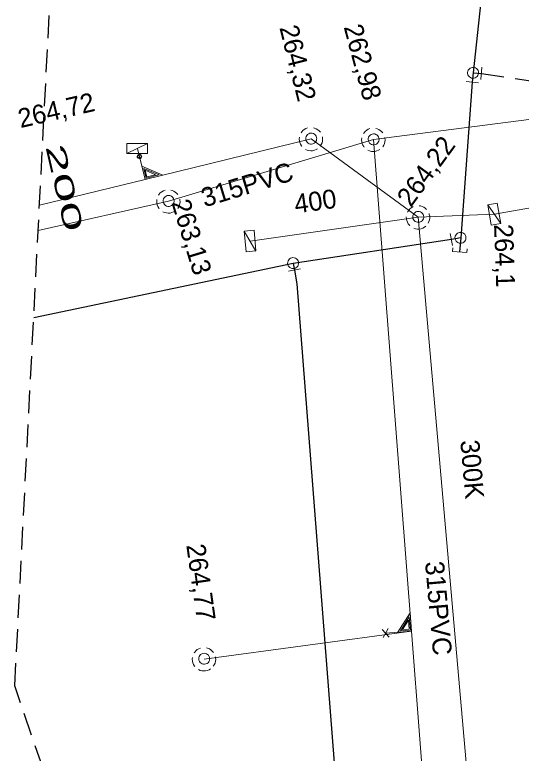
# Model space of a CAD drawing. Extents: x -732074 to -731966, y -1048695 to -1047982.
# Drawn here: x -732074 to -732052.65, y -1048415.55 to -1048384.41 of the extents above; entities that cross this region are included whole.
import ezdxf

# ---------------------------------------------------------------- set-up
doc = ezdxf.new("R2010")
doc.units = 0
doc.header["$LTSCALE"] = 0.32
doc.linetypes.add('LONG_DASHED', pattern=[7.5, 6, -1.5])
doc.linetypes.add('MEDIUM_DASHED', pattern=[4.5, 3, -1.5])
doc.layers.add('1', color=7, linetype='Continuous')
for name, color, linetype, lineweight in [('18', 7, 'Continuous', 13), ('20', 7, 'Continuous', 13), ('49', 7, 'Continuous', 13), ('63', 7, 'MEDIUM_DASHED', 25), ('8', 7, 'Continuous', 13)]:
    doc.layers.add(name, color=color, linetype=linetype, lineweight=lineweight)

msp = doc.modelspace()

# ---------------------------------------------------------------- linework, layer by layer
at = {"layer": '18'}
for p, q in [((-732069.271, -1048390.25), (-732068.397, -1048389.838)), ((-732054.062, -1048392.419), (-732053.508, -1048393.211)), ((-732064.32, -1048393.539), (-732063.829, -1048394.371)), ((-732058.507, -1048410.339), (-732058.213, -1048410.653)), ((-732058.468, -1048410.676), (-732058.253, -1048410.288))]:
    msp.add_line(p, q, dxfattribs=at)
for points in [[(-732061.653, -1048389.177), (-732061.724, -1048389.205), (-732061.791, -1048389.244), (-732061.851, -1048389.292), (-732061.902, -1048389.349), (-732061.926, -1048389.383)], [(-732061.112, -1048389.36), (-732061.162, -1048389.302), (-732061.22, -1048389.252), (-732061.285, -1048389.211), (-732061.356, -1048389.182), (-732061.405, -1048389.168)], [(-732059.023, -1048389.207), (-732059.094, -1048389.235), (-732059.161, -1048389.274), (-732059.221, -1048389.322), (-732059.272, -1048389.379), (-732059.296, -1048389.413)], [(-732058.482, -1048389.39), (-732058.532, -1048389.332), (-732058.59, -1048389.282), (-732058.655, -1048389.241), (-732058.726, -1048389.212), (-732058.775, -1048389.198)], [(-732061.998, -1048389.569), (-732062.004, -1048389.646), (-732061.999, -1048389.723), (-732061.982, -1048389.798), (-732061.953, -1048389.869), (-732061.913, -1048389.935), (-732061.897, -1048389.957)], [(-732061.117, -1048389.946), (-732061.076, -1048389.881), (-732061.045, -1048389.811), (-732061.026, -1048389.736), (-732061.018, -1048389.66), (-732061.023, -1048389.583), (-732061.029, -1048389.548)], [(-732058.487, -1048389.976), (-732058.446, -1048389.911), (-732058.415, -1048389.841), (-732058.396, -1048389.766), (-732058.388, -1048389.69), (-732058.393, -1048389.613), (-732058.399, -1048389.578)], [(-732059.368, -1048389.599), (-732059.374, -1048389.676), (-732059.369, -1048389.753), (-732059.352, -1048389.828), (-732059.323, -1048389.899), (-732059.282, -1048389.965), (-732059.267, -1048389.987)], [(-732061.74, -1048390.086), (-732061.67, -1048390.117), (-732061.595, -1048390.136), (-732061.519, -1048390.143), (-732061.442, -1048390.138), (-732061.367, -1048390.121), (-732061.295, -1048390.093), (-732061.235, -1048390.058)], [(-732059.11, -1048390.116), (-732059.04, -1048390.147), (-732058.965, -1048390.166), (-732058.889, -1048390.173), (-732058.812, -1048390.168), (-732058.737, -1048390.151), (-732058.665, -1048390.123), (-732058.605, -1048390.088)], [(-732068.763, -1048390.288), (-732068.503, -1048391.352), (-732067.754, -1048391.169), (-732068.64, -1048390.79)], [(-732068.562, -1048390.894), (-732068.464, -1048391.298), (-732067.914, -1048391.163), (-732068.563, -1048390.892)], [(-732068.497, -1048390.963), (-732068.428, -1048391.247), (-732068.067, -1048391.159), (-732068.498, -1048390.964)], [(-732067.663, -1048391.807), (-732067.734, -1048391.835), (-732067.801, -1048391.874), (-732067.861, -1048391.922), (-732067.912, -1048391.979), (-732067.936, -1048392.013)], [(-732067.122, -1048391.99), (-732067.172, -1048391.932), (-732067.23, -1048391.882), (-732067.295, -1048391.841), (-732067.366, -1048391.812), (-732067.415, -1048391.798)], [(-732068.008, -1048392.199), (-732068.014, -1048392.276), (-732068.009, -1048392.353), (-732067.992, -1048392.428), (-732067.963, -1048392.499), (-732067.923, -1048392.565), (-732067.907, -1048392.587)], [(-732067.127, -1048392.576), (-732067.086, -1048392.511), (-732067.055, -1048392.441), (-732067.036, -1048392.366), (-732067.028, -1048392.29), (-732067.033, -1048392.213), (-732067.039, -1048392.178)], [(-732067.75, -1048392.716), (-732067.68, -1048392.747), (-732067.605, -1048392.766), (-732067.529, -1048392.773), (-732067.452, -1048392.768), (-732067.377, -1048392.751), (-732067.305, -1048392.723), (-732067.245, -1048392.688)], [(-732057.196, -1048392.499), (-732057.263, -1048392.535), (-732057.325, -1048392.582), (-732057.378, -1048392.636), (-732057.422, -1048392.699), (-732057.442, -1048392.736)], [(-732056.637, -1048392.616), (-732056.693, -1048392.564), (-732056.757, -1048392.521), (-732056.826, -1048392.488), (-732056.9, -1048392.468), (-732056.95, -1048392.46)], [(-732057.491, -1048392.929), (-732057.488, -1048393.006), (-732057.474, -1048393.082), (-732057.448, -1048393.154), (-732057.411, -1048393.221), (-732057.363, -1048393.282), (-732057.345, -1048393.302)], [(-732056.572, -1048393.198), (-732056.539, -1048393.129), (-732056.516, -1048393.055), (-732056.506, -1048392.979), (-732056.507, -1048392.902), (-732056.522, -1048392.827), (-732056.532, -1048392.792)], [(-732057.174, -1048393.411), (-732057.1, -1048393.434), (-732057.024, -1048393.444), (-732056.947, -1048393.442), (-732056.871, -1048393.428), (-732056.799, -1048393.402), (-732056.731, -1048393.365), (-732056.675, -1048393.323)], [(-732058.366, -1048410.49), (-732057.273, -1048410.406), (-732057.333, -1048409.637), (-732057.85, -1048410.45)], [(-732057.736, -1048410.39), (-732057.321, -1048410.358), (-732057.365, -1048409.795), (-732057.737, -1048410.39)], [(-732057.656, -1048410.337), (-732057.366, -1048410.315), (-732057.394, -1048409.945), (-732057.656, -1048410.339)], [(-732066.163, -1048411.117), (-732066.234, -1048411.145), (-732066.301, -1048411.184), (-732066.361, -1048411.232), (-732066.412, -1048411.289), (-732066.436, -1048411.323)], [(-732065.622, -1048411.3), (-732065.672, -1048411.242), (-732065.73, -1048411.192), (-732065.795, -1048411.151), (-732065.866, -1048411.122), (-732065.915, -1048411.108)], [(-732066.508, -1048411.509), (-732066.514, -1048411.586), (-732066.509, -1048411.663), (-732066.492, -1048411.738), (-732066.463, -1048411.809), (-732066.423, -1048411.875), (-732066.407, -1048411.897)], [(-732065.627, -1048411.886), (-732065.586, -1048411.821), (-732065.555, -1048411.751), (-732065.536, -1048411.676), (-732065.528, -1048411.6), (-732065.533, -1048411.523), (-732065.539, -1048411.488)], [(-732066.25, -1048412.026), (-732066.18, -1048412.057), (-732066.105, -1048412.076), (-732066.029, -1048412.083), (-732065.952, -1048412.078), (-732065.877, -1048412.061), (-732065.805, -1048412.033), (-732065.745, -1048411.998)]]:
    msp.add_lwpolyline(points, dxfattribs=at)
for points in [[(-732061.269, -1048389.629), (-732061.275, -1048389.577), (-732061.293, -1048389.527), (-732061.321, -1048389.483), (-732061.359, -1048389.446), (-732061.404, -1048389.419), (-732061.454, -1048389.403), (-732061.506, -1048389.398), (-732061.558, -1048389.405), (-732061.607, -1048389.424), (-732061.651, -1048389.454), (-732061.686, -1048389.493), (-732061.712, -1048389.538), (-732061.727, -1048389.589), (-732061.73, -1048389.641), (-732061.722, -1048389.693), (-732061.701, -1048389.741), (-732061.671, -1048389.784), (-732061.631, -1048389.819), (-732061.585, -1048389.843), (-732061.534, -1048389.857), (-732061.482, -1048389.859), (-732061.43, -1048389.849), (-732061.382, -1048389.827), (-732061.34, -1048389.795), (-732061.307, -1048389.755), (-732061.283, -1048389.708), (-732061.271, -1048389.657)], [(-732058.639, -1048389.659), (-732058.645, -1048389.607), (-732058.663, -1048389.557), (-732058.691, -1048389.513), (-732058.729, -1048389.476), (-732058.774, -1048389.449), (-732058.824, -1048389.433), (-732058.876, -1048389.428), (-732058.928, -1048389.435), (-732058.977, -1048389.454), (-732059.021, -1048389.484), (-732059.056, -1048389.523), (-732059.082, -1048389.568), (-732059.097, -1048389.619), (-732059.1, -1048389.671), (-732059.092, -1048389.723), (-732059.071, -1048389.771), (-732059.041, -1048389.814), (-732059.001, -1048389.849), (-732058.955, -1048389.873), (-732058.904, -1048389.887), (-732058.852, -1048389.889), (-732058.8, -1048389.879), (-732058.752, -1048389.857), (-732058.71, -1048389.825), (-732058.677, -1048389.785), (-732058.653, -1048389.738), (-732058.641, -1048389.687)], [(-732069.275, -1048389.838), (-732068.401, -1048389.838), (-732068.401, -1048390.25), (-732069.275, -1048390.25)], [(-732068.649, -1048390.357), (-732068.662, -1048390.326), (-732068.686, -1048390.302), (-732068.716, -1048390.288), (-732068.749, -1048390.286), (-732068.781, -1048390.295), (-732068.808, -1048390.315), (-732068.827, -1048390.343), (-732068.834, -1048390.376), (-732068.83, -1048390.409), (-732068.814, -1048390.439), (-732068.789, -1048390.46), (-732068.758, -1048390.472), (-732068.724, -1048390.472), (-732068.693, -1048390.461), (-732068.667, -1048390.44), (-732068.651, -1048390.41), (-732068.646, -1048390.377)], [(-732068.674, -1048390.365), (-732068.687, -1048390.34), (-732068.709, -1048390.321), (-732068.735, -1048390.313), (-732068.764, -1048390.318), (-732068.787, -1048390.333), (-732068.803, -1048390.357), (-732068.808, -1048390.385), (-732068.8, -1048390.412), (-732068.781, -1048390.434), (-732068.756, -1048390.446), (-732068.727, -1048390.447), (-732068.702, -1048390.437), (-732068.683, -1048390.416), (-732068.673, -1048390.389)], [(-732067.279, -1048392.259), (-732067.285, -1048392.207), (-732067.303, -1048392.157), (-732067.331, -1048392.113), (-732067.369, -1048392.076), (-732067.414, -1048392.049), (-732067.464, -1048392.033), (-732067.516, -1048392.028), (-732067.568, -1048392.035), (-732067.617, -1048392.054), (-732067.661, -1048392.084), (-732067.696, -1048392.123), (-732067.722, -1048392.168), (-732067.737, -1048392.219), (-732067.74, -1048392.271), (-732067.732, -1048392.323), (-732067.711, -1048392.371), (-732067.681, -1048392.414), (-732067.641, -1048392.449), (-732067.595, -1048392.473), (-732067.544, -1048392.487), (-732067.492, -1048392.489), (-732067.44, -1048392.479), (-732067.392, -1048392.457), (-732067.35, -1048392.425), (-732067.317, -1048392.385), (-732067.293, -1048392.338), (-732067.281, -1048392.287)], [(-732053.656, -1048392.346), (-732053.509, -1048393.207), (-732053.915, -1048393.277), (-732054.062, -1048392.416)], [(-732056.757, -1048392.929), (-732056.764, -1048392.877), (-732056.781, -1048392.827), (-732056.809, -1048392.783), (-732056.848, -1048392.746), (-732056.892, -1048392.719), (-732056.943, -1048392.703), (-732056.995, -1048392.698), (-732057.046, -1048392.705), (-732057.095, -1048392.724), (-732057.139, -1048392.754), (-732057.174, -1048392.793), (-732057.201, -1048392.838), (-732057.215, -1048392.889), (-732057.218, -1048392.941), (-732057.21, -1048392.993), (-732057.19, -1048393.041), (-732057.159, -1048393.084), (-732057.12, -1048393.119), (-732057.073, -1048393.143), (-732057.022, -1048393.157), (-732056.97, -1048393.159), (-732056.919, -1048393.149), (-732056.87, -1048393.127), (-732056.828, -1048393.095), (-732056.796, -1048393.055), (-732056.772, -1048393.008), (-732056.759, -1048392.957)], [(-732063.91, -1048393.497), (-732063.83, -1048394.367), (-732064.24, -1048394.405), (-732064.32, -1048393.535)], [(-732065.779, -1048411.569), (-732065.785, -1048411.517), (-732065.803, -1048411.467), (-732065.831, -1048411.423), (-732065.869, -1048411.386), (-732065.914, -1048411.359), (-732065.964, -1048411.343), (-732066.016, -1048411.338), (-732066.068, -1048411.345), (-732066.117, -1048411.364), (-732066.161, -1048411.394), (-732066.196, -1048411.433), (-732066.222, -1048411.478), (-732066.237, -1048411.529), (-732066.24, -1048411.581), (-732066.232, -1048411.633), (-732066.211, -1048411.681), (-732066.181, -1048411.724), (-732066.141, -1048411.759), (-732066.095, -1048411.783), (-732066.044, -1048411.797), (-732065.992, -1048411.799), (-732065.94, -1048411.789), (-732065.892, -1048411.767), (-732065.85, -1048411.735), (-732065.817, -1048411.695), (-732065.793, -1048411.648), (-732065.781, -1048411.597)]]:
    msp.add_lwpolyline(points, close=True, dxfattribs=at)
at = {"layer": '20'}
for p, q in [((-732067.51, -1048392.27), (-732058.87, -1048389.67)), ((-732067.51, -1048392.27), (-732058.87, -1048389.67)), ((-732061.5, -1048389.64), (-732056.989, -1048392.94)), ((-732061.5, -1048389.64), (-732056.989, -1048392.94)), ((-732073.01, -1048393.503), (-732067.51, -1048392.27)), ((-732073.01, -1048393.503), (-732067.51, -1048392.27)), ((-732064.07, -1048393.96), (-732056.989, -1048392.94)), ((-732064.07, -1048393.96), (-732056.989, -1048392.94)), ((-732056.989, -1048392.94), (-732053.78, -1048392.82)), ((-732056.989, -1048392.94), (-732053.78, -1048392.82)), ((-732053.92, -1048427.8), (-732056.989, -1048392.94)), ((-732053.92, -1048427.8), (-732056.989, -1048392.94))]:
    msp.add_line(p, q, dxfattribs=at)
at = {"layer": '20', "linetype": 'LONG_DASHED'}
msp.add_line((-732053.78, -1048392.82), (-732046.694, -1048391.564), dxfattribs=at)
msp.add_line((-732053.78, -1048392.82), (-732046.694, -1048391.564), dxfattribs=at)
at = {"layer": '20'}
for points in [[(-732058.87, -1048389.67), (-732043.269, -1048387.661), (-732041.707, -1048387.459)], [(-732058.87, -1048389.67), (-732043.269, -1048387.661), (-732041.707, -1048387.459)], [(-732072.956, -1048392.443), (-732068.504, -1048391.354), (-732061.5, -1048389.64)], [(-732072.956, -1048392.443), (-732068.504, -1048391.354), (-732061.5, -1048389.64)], [(-732055.579, -1048432.35), (-732056.217, -1048424.068), (-732057.272, -1048410.408), (-732058.87, -1048389.67)], [(-732055.579, -1048432.35), (-732056.217, -1048424.068), (-732057.272, -1048410.408), (-732058.87, -1048389.67)]]:
    msp.add_lwpolyline(points, dxfattribs=at)
at = {"layer": '49'}
for p, q in [((-732068.829, -1048390.04), (-732068.504, -1048391.354)), ((-732068.829, -1048390.04), (-732068.504, -1048391.354)), ((-732066.01, -1048411.58), (-732057.272, -1048410.408)), ((-732066.01, -1048411.58), (-732057.272, -1048410.408))]:
    msp.add_line(p, q, dxfattribs=at)
at = {"layer": '63'}
msp.add_lwpolyline([(-732022.871, -1048561.909), (-732073.995, -1048412.717), (-732073.996, -1048412.715), (-732073.996, -1048412.713), (-732069.268, -1048320.574)], dxfattribs=at)
at = {"layer": '8'}
for p, q in [((-732054.303, -1048386.621), (-732054.354, -1048387.136)), ((-732054.451, -1048387.277), (-732054.966, -1048387.222)), ((-732055.539, -1048394.143), (-732055.638, -1048393.636)), ((-732061.951, -1048395.125), (-732062.458, -1048395.222))]:
    msp.add_line(p, q, dxfattribs=at)
at = {"layer": '8', "lineweight": 25}
for p, q in [((-732054.669, -1048386.855), (-732054.71, -1048387.25)), ((-732054.669, -1048386.855), (-732054.329, -1048386.88)), ((-732054.71, -1048387.25), (-732055.199, -1048393.814)), ((-732055.589, -1048393.89), (-732062.264, -1048394.892)), ((-732055.199, -1048393.814), (-732055.589, -1048393.89)), ((-732062.264, -1048394.892), (-732073.199, -1048397.189)), ((-732062.264, -1048394.892), (-732062.206, -1048395.174))]:
    msp.add_line(p, q, dxfattribs=at)
at = {"layer": '8', "linetype": 'MEDIUM_DASHED', "lineweight": 25}
for p, q in [((-732054.329, -1048386.88), (-732048.844, -1048387.71)), ((-732055.199, -1048393.814), (-732055.245, -1048394.411))]:
    msp.add_line(p, q, dxfattribs=at)
at = {"layer": '8', "lineweight": 25}
for points in [[(-732044.76, -1048309.89), (-732045.27, -1048311.67), (-732051.3, -1048355.421), (-732054.669, -1048386.855)], [(-732062.206, -1048395.174), (-732062.1, -1048395.76), (-732060.37, -1048418.12)]]:
    msp.add_lwpolyline(points, dxfattribs=at)
at = {"layer": '8'}
for points in [[(-732054.654, -1048386.624), (-732054.707, -1048386.624), (-732054.758, -1048386.637), (-732054.805, -1048386.66), (-732054.846, -1048386.694), (-732054.878, -1048386.736), (-732054.899, -1048386.784), (-732054.909, -1048386.835), (-732054.908, -1048386.887), (-732054.894, -1048386.938), (-732054.869, -1048386.985), (-732054.834, -1048387.024), (-732054.792, -1048387.054), (-732054.743, -1048387.075), (-732054.692, -1048387.083), (-732054.639, -1048387.081), (-732054.589, -1048387.065), (-732054.543, -1048387.04), (-732054.504, -1048387.004), (-732054.475, -1048386.961), (-732054.456, -1048386.911), (-732054.448, -1048386.86), (-732054.453, -1048386.807), (-732054.469, -1048386.757), (-732054.497, -1048386.712), (-732054.533, -1048386.675), (-732054.577, -1048386.646), (-732054.627, -1048386.629)], [(-732055.191, -1048393.582), (-732055.243, -1048393.584), (-732055.294, -1048393.598), (-732055.34, -1048393.623), (-732055.38, -1048393.658), (-732055.411, -1048393.7), (-732055.431, -1048393.749), (-732055.44, -1048393.8), (-732055.437, -1048393.853), (-732055.422, -1048393.903), (-732055.395, -1048393.949), (-732055.359, -1048393.987), (-732055.317, -1048394.017), (-732055.267, -1048394.036), (-732055.215, -1048394.043), (-732055.163, -1048394.039), (-732055.113, -1048394.022), (-732055.068, -1048393.995), (-732055.03, -1048393.958), (-732055.002, -1048393.914), (-732054.984, -1048393.865), (-732054.978, -1048393.813), (-732054.984, -1048393.76), (-732055.002, -1048393.711), (-732055.031, -1048393.666), (-732055.068, -1048393.63), (-732055.113, -1048393.603), (-732055.163, -1048393.587)], [(-732062.032, -1048394.881), (-732062.039, -1048394.829), (-732062.056, -1048394.779), (-732062.085, -1048394.735), (-732062.123, -1048394.698), (-732062.168, -1048394.671), (-732062.218, -1048394.655), (-732062.27, -1048394.65), (-732062.321, -1048394.657), (-732062.37, -1048394.676), (-732062.414, -1048394.706), (-732062.45, -1048394.745), (-732062.476, -1048394.79), (-732062.49, -1048394.841), (-732062.494, -1048394.893), (-732062.485, -1048394.945), (-732062.465, -1048394.993), (-732062.434, -1048395.036), (-732062.395, -1048395.071), (-732062.348, -1048395.095), (-732062.298, -1048395.109), (-732062.245, -1048395.111), (-732062.194, -1048395.101), (-732062.146, -1048395.079), (-732062.103, -1048395.047), (-732062.071, -1048395.007), (-732062.047, -1048394.96), (-732062.034, -1048394.909)]]:
    msp.add_lwpolyline(points, close=True, dxfattribs=at)
msp.add_lwpolyline([(-732054.923, -1048394.283), (-732054.935, -1048394.438), (-732055.54, -1048394.39), (-732055.528, -1048394.236)], dxfattribs=at)

# ---------------------------------------------------------------- texts
at = {"layer": '1'}
for s, rotation, p in [('264,32', 284, (-732062.844, -1048384.948)), ('262,98', 285, (-732060.136, -1048384.919)), ('264,72', 13, (-732073.753, -1048389.187)), ('264,22', 54, (-732057.302, -1048392.557)), ('315PVC', 17, (-732065.993, -1048392.532)), ('400 ', 8, (-732062.156, -1048392.788)), ('263,13', 287, (-732067.397, -1048392.325)), ('264,1 ', 272, (-732053.794, -1048393.243)), ('300K', 275, (-732055.217, -1048402.37)), ('264,77', 278, (-732066.769, -1048406.775)), ('315PVC', 275, (-732056.704, -1048407.488))]:
    msp.add_text(s, height=0.8, rotation=rotation, dxfattribs=at).set_placement(p)
at = {"layer": '1', "width": 2.1}
msp.add_text('200 ', height=0.8, rotation=283, dxfattribs=at).set_placement((-732072.711, -1048389.959))

doc.saveas('drawing.dxf')
